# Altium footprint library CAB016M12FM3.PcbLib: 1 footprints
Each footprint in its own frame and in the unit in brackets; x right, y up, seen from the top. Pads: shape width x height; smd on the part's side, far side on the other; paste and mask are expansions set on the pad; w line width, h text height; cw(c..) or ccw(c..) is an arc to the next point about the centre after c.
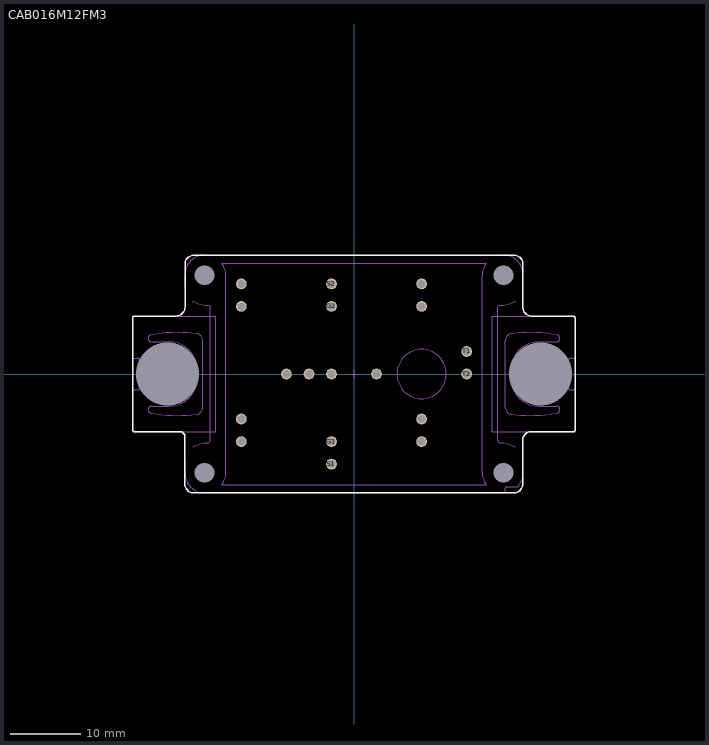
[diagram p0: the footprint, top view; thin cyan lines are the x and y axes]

## CAB016M12FM3 [mm] "CAB016M12FM3 Footprint"
pads (24):
  round 1.524 hole 1.1: AC_1(9.6,12.8) AC_2(9.6,9.6) AC_3(-16,12.8) AC_4(-16,9.6) DC+_1(9.6,-6.4) DC+_2(9.6,-9.6) DC+_3(-16,-6.4) DC+_4(-16,-9.6) DC-_1(3.2,0) DC-_2(-3.2,0) DC-_3(-6.4,0) DC-_4(-9.6,0) G1(-3.2,-9.6) G2(-3.2,9.6) S1(-3.2,-12.8) S2(-3.2,12.8) T1(16,3.2) T2(16,0)
  round 0.099 / inner round 1.524 / far side round 0.099 hole 8.999 unplated: ""(-26.5,0) ""(26.5,0)
  round 0.099 hole 2.794 unplated: ""(-21.25,-14.05)
  round 0.099 / inner round 1.524 / far side round 0.099 hole 2.794 unplated: ""(-21.25,14.05) ""(21.25,-14.05) ""(21.25,14.05)
Top Overlay:
  lines w0.2: -31.419,-7.975 ccw(c-31.202,-7.975) -31.202,-8.191 -24.712,-8.191 cw(c-24.712,-8.867) -24.036,-8.867 -24.036,-15.634 ccw(c-22.766,-15.634) -22.766,-16.904 22.684,-16.904 ccw(c22.684,-15.634) 23.954,-15.634 23.954,-9.448 cw(c25.224,-9.448) 25.224,-8.178 31.236,-8.178 ccw(c31.236,-8.01) 31.404,-8.01 31.404,7.928 ccw(c31.132,7.928) 31.132,8.2 25.27,8.2 cw(c25.27,9.47) 24,9.47 24,15.604 ccw(c22.73,15.604) 22.73,16.874 -17.453,16.874 -22.759,16.874 ccw(c-22.759,15.633) -24,15.633 -24,9.499 cw(c-25.27,9.499) -25.27,8.229 -31.254,8.229 ccw(c-31.254,8.064) -31.419,8.064 -31.419,-7.975
Bottom Overlay:
  text "CAB016M12FM3" at 23.246,18.754 h1.52
Mechanical 1:
  text "Hole sizes and tolerances should be checked for the final application (press-fit, soldered, pin receptacles)" at -18.5,19 h1.52
Mechanical 5:
  text "DC-" at 2.5,2 h0.64
  text "DC-" at -4,2 h0.64
  text "DC-" at -7.5,2 h0.64
  text "DC-" at -10,2 h0.64
  text "AC" at 11.5,9 h0.64
  text "AC" at 11.5,12.5 h0.64
  text "AC" at -13.5,9 h0.64
  text "DC+" at -14,-6.4 h0.64
  text "DC+" at -14,-10 h0.64
  text "DC+" at 5.5,-6.5 h0.64
  text "DC+" at 5.5,-10 h0.64
  text "G1" at -1.5,-10 h0.64
  text "S1" at -1.5,-13 h0.64
  text "T2" at 13.5,-0.5 h0.64
  text "T1" at 13.5,3 h0.64
  text "S2" at -1.5,12.5 h0.64
  text "G2" at -1.5,9.5 h0.64
  text "AC" at -13.5,12.5 h0.64
Mechanical 6:
  circle w0.025: c-21.25,-14.05 r1.151
  circle w0.025: c21.25,-14.05 r1.15
  circle w0.025: c9.6,0 r3.496
  circle w0.025: c-21.25,14.05 r1.151
  circle w0.025: c21.25,14.05 r1.15
  lines w0.025: -28.999,0 -24,0 ; -24,-12.499 -24,-14.1 ccw(c-21.2,-14.101) -21.199,-16.901 21.199,-16.901 ccw(c21.154,-14.102) 21.328,-16.896 21.45,-16.848 21.519,-16.698 21.519,-16.2 cw(c21.719,-16.2) 21.72,-15.999 23.167,-15.999 23.241,-15.984 23.32,-15.931 ccw(c21.2,-14.101) 24,-14.1 24,-12.499 ; -24,12.499 -24,14.1 cw(c-21.2,14.101) -21.199,16.901 21.199,16.901 cw(c21.2,14.101) 24,14.1 24,12.499 ; -22.898,-10.274 -22.83,-10.363 -21.946,-9.914 -21.176,-9.802 -20.775,-9.802 -20.615,-9.766 -20.508,-9.693 -20.419,-9.553 -20.396,-9.426 -20.396,9.426 -20.434,9.586 -20.508,9.693 -20.648,9.779 -20.775,9.802 -21.176,9.802 -22.149,9.982 -22.83,10.363 -22.898,10.274 ; 22.898,-10.274 22.83,-10.363 22.149,-9.982 21.176,-9.802 20.775,-9.802 20.648,-9.779 20.508,-9.693 20.434,-9.586 20.396,-9.426 20.396,9.426 20.419,9.553 20.508,9.693 20.615,9.766 20.775,9.802 21.176,9.802 21.946,9.914 22.83,10.363 22.898,10.274 ; 24,0 28.999,0 ; 31.399,-8.199 30.599,-8.199 19.649,-8.199 19.649,8.199 30.599,8.199 31.399,8.199 ; 31.399,-2.25 30.8,-2.25 cw(c30.799,-1.85) 30.599,-2.197 cw(c30.801,-1.852) 30.401,-1.849 30.401,1.849 cw(c30.801,1.852) 30.599,2.197 cw(c30.799,1.85) 30.8,2.25 31.399,2.25 ; -31.399,-8.199 -30.599,-8.199 -19.649,-8.199 -19.649,8.199 -30.599,8.199 -31.399,8.199 -31.399,2.25 -30.8,2.25 cw(c-30.799,1.85) -30.599,2.197 cw(c-30.801,1.852) -30.401,1.849 -30.401,-1.849 cw(c-30.801,-1.852) -30.599,-2.197 cw(c-30.799,-1.85) -30.8,-2.25 -31.399,-2.25 -31.399,-8.199 ; -28.755,-5.547 ccw(c-24.999,14.3) -22.37,-5.728 ccw(c-22.501,-4.737) -21.501,-4.737 -21.501,4.737 ccw(c-22.501,4.737) -22.37,5.728 ccw(c-25.006,-14.3) -25.001,5.9 ccw(c-24.995,-14.3) -28.755,5.547 ccw(c-28.755,5.048) -28.755,4.549 -26.269,4.549 cw(c-26.267,0.548) -22.619,2.189 cw(c-27.485,0) -22.619,-2.189 cw(c-26.267,-0.548) -26.269,-4.549 -28.755,-4.549 ccw(c-28.755,-5.048) -28.755,-5.547 ; -26.749,-2.25 cw(c-26.75,0) -26.749,2.25 -26.251,2.25 cw(c-26.25,0) -26.251,-2.25 -26.749,-2.25 ; -18.819,-15.748 ccw(c-21.204,-13.929) -18.204,-13.927 -18.204,13.927 ccw(c-21.204,13.929) -18.819,15.748 18.819,15.748 ccw(c21.204,13.929) 18.204,13.927 18.204,-13.927 ccw(c21.204,-13.929) 18.819,-15.748 -18.819,-15.748 ; 21.501,-4.737 ccw(c22.501,-4.737) 22.37,-5.728 ccw(c25.006,14.3) 25.001,-5.9 ccw(c24.995,14.3) 28.755,-5.547 ccw(c28.755,-5.048) 28.755,-4.549 26.269,-4.549 cw(c26.267,-0.548) 22.619,-2.189 cw(c27.485,0) 22.619,2.189 cw(c26.267,0.548) 26.269,4.549 28.755,4.549 ccw(c28.755,5.048) 28.755,5.547 ccw(c24.999,-14.3) 22.37,5.728 ccw(c22.501,4.737) 21.501,4.737 21.501,-4.737 ; 26.251,-2.25 cw(c26.25,0) 26.251,2.25 26.749,2.25 cw(c26.75,0) 26.749,-2.25 26.251,-2.25
Mechanical 8:
  lines w0.025: -0.635,0 0.635,0 ; 0,-0.635 0,0.635
3D body "CAB011M12FM3.STEP": height 13.33, standoff -3.07, extent -31.4,-16.9 31.4,16.9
